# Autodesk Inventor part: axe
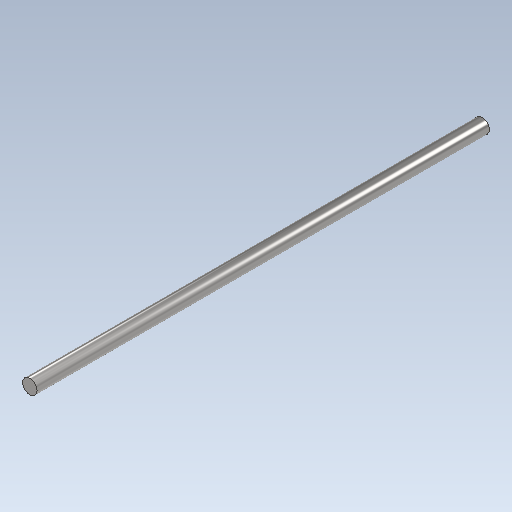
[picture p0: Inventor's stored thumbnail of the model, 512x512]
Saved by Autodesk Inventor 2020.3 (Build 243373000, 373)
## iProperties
Created: 2020-09
Part Number: axe
Material: Acier, alliage
Document SubType Name: Modeling
Designer: ficho
Density: 7.73 g/cm^3
Appearance: Semi-poli
Mass: 0.189555 g
Surface Area: 0.996594 cm^2
Volume: 0.024522 cm^3
Author: ficho
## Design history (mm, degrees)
sketch "Esquisse1"
  geometry: C1 r 0.5 at (-0.01, -0.75) reference; 1 further point
  node "Référence1"
node "Plan de construction1"
extrude "Extrusion1" new body sketch "Esquisse1" stored distance "d0" = 10; taper "d1" = 0 deg
node "Solide1"
